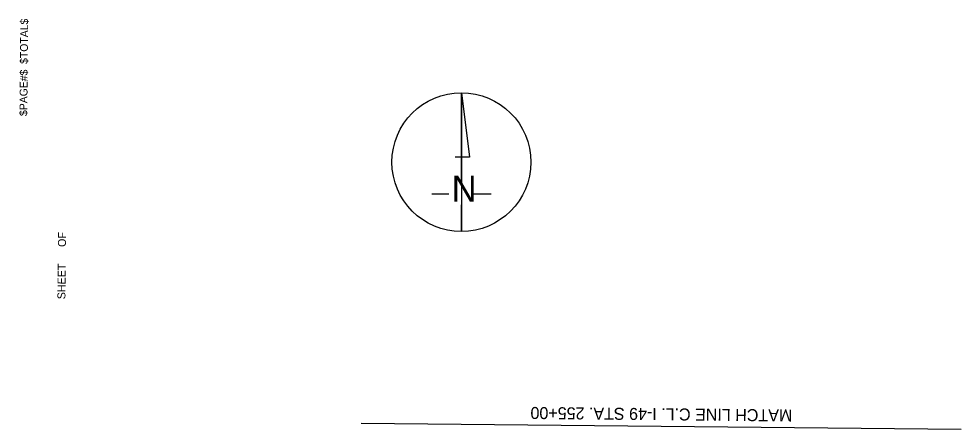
# Model space of a CAD drawing. Extents: x 631402 to 632816, y 379903 to 382944.
import ezdxf

# ---------------------------------------------------------------- set-up
doc = ezdxf.new("R2010")
doc.units = 0
for name, color, linetype in [('R_Border', 7, 'Continuous'), ('R_Border Notes', 7, 'Continuous'), ('R_Border_N Arrow', 7, 'Continuous'), ('R_No Plot', 7, 'Continuous')]:
    doc.layers.add(name, color=color, linetype=linetype)

msp = doc.modelspace()

# ---------------------------------------------------------------- linework, layer by layer
at = {"layer": 'R_Border'}
msp.add_line((631915.6, 382336.7), (632815.6, 382327.7), dxfattribs=at)
at = {"layer": 'R_Border_N Arrow'}
for p, q in [((632066.1, 382832.8), (632078.3, 382735.8)), ((632066.1, 382697.2), (632066.1, 382832.8)), ((632056.7, 382736.5), (632078.3, 382736.5)), ((632021.5, 382681.2), (632047.3, 382681.2)), ((632083.2, 382681.2), (632110.7, 382681.2)), ((632066.1, 382624.5), (632066.1, 382664.3))]:
    msp.add_line(p, q, dxfattribs=at)
at = {"layer": 'R_No Plot'}
msp.add_line((632066.1, 382832.8), (632066.1, 382624.5), dxfattribs=at)
msp.add_circle((632066.1, 382728.6), 104.2, dxfattribs=at)

# ---------------------------------------------------------------- texts
at = {"layer": 'R_Border'}
for s, p in [('$TOTAL$', (631415.7, 382875.9)), ('$PAGE#$', (631415, 382797.7))]:
    msp.add_text(s, height=11.72, rotation=89.4304, dxfattribs=at).set_placement(p)
at = {"layer": 'R_Border Notes'}
msp.add_text('MATCH LINE C.L. I-49 STA. 255+00', height=18, rotation=179.4304, dxfattribs=at).set_placement((632562.4, 382357.2))
at = {"layer": 'R_Border_N Arrow'}
msp.add_text('N', height=38.8, rotation=360, dxfattribs=at).set_placement((632051.4, 382669.3))
at = {"layer": 'R_No Plot'}
for s, p in [('OF', (631473, 382601.2)), ('SHEET', (631472.2, 382522.7))]:
    msp.add_text(s, height=12, rotation=89.4304, dxfattribs=at).set_placement(p)

doc.saveas('drawing.dxf')
